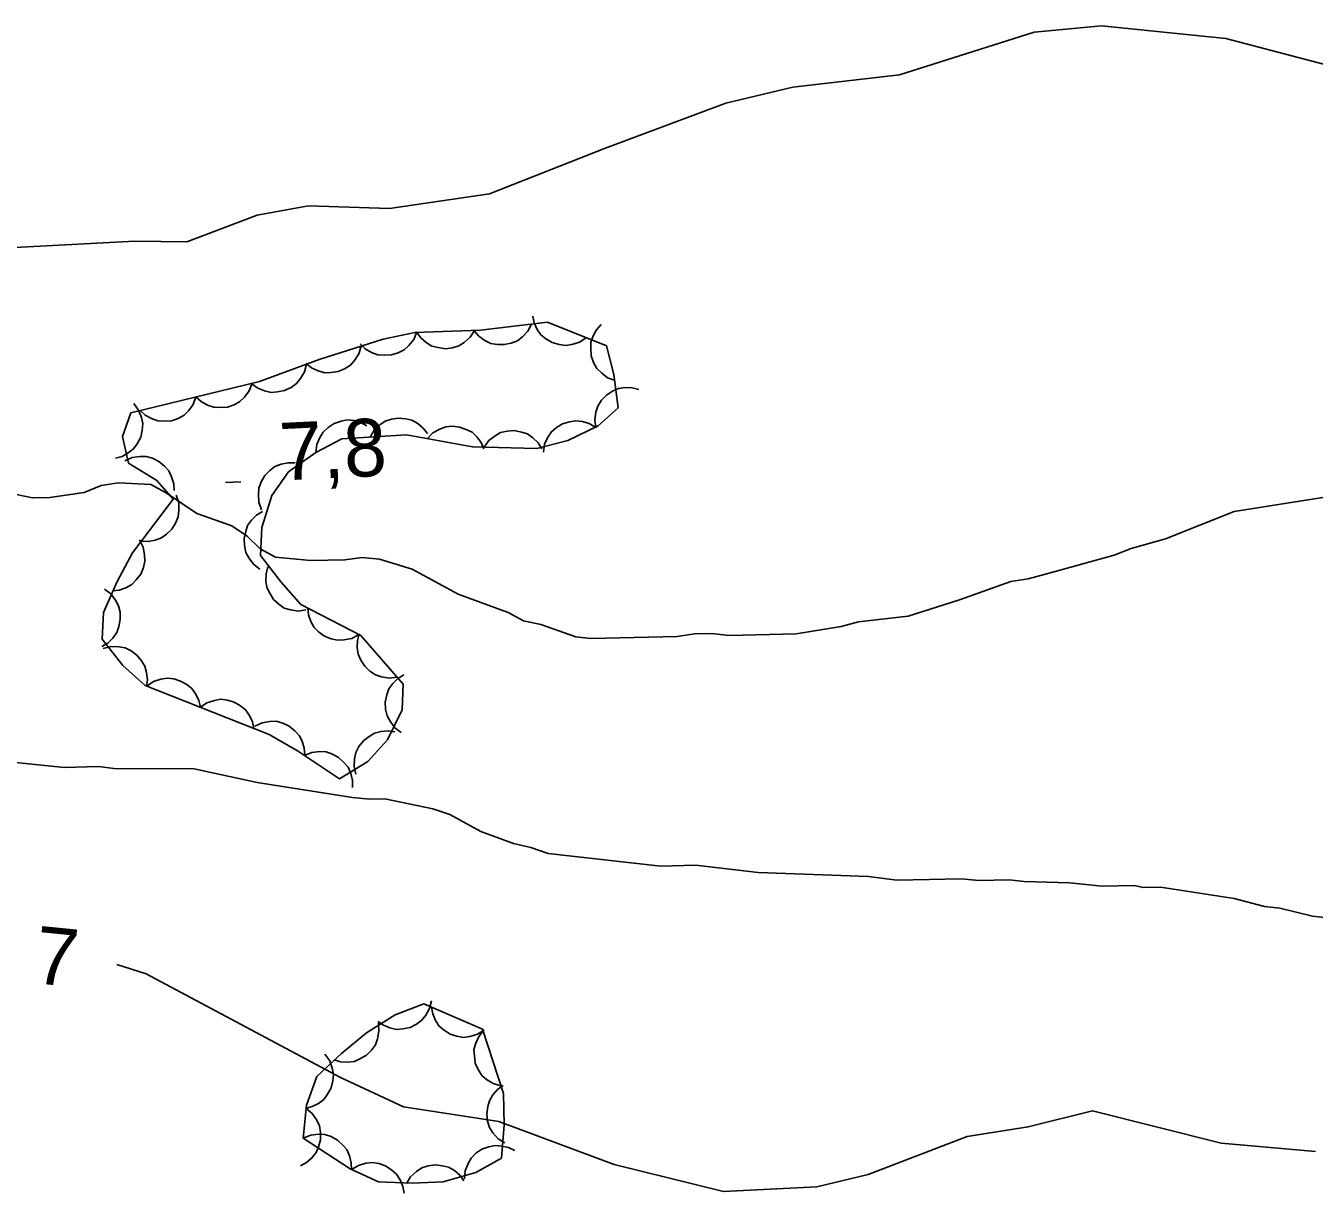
# Model space of a CAD drawing. Extents: x 336540 to 340074, y 5572036 to 5573747.
# Drawn here: x 337020.3 to 337087.4, y 5573140.7 to 5573201.5 of the extents above; entities that cross this region are included whole.
import ezdxf

# ---------------------------------------------------------------- set-up
doc = ezdxf.new("R2010")
doc.units = 0
for name, color, linetype in [('Niveau 2', 7, 'Continuous'), ('Niveau 3', 7, 'Continuous'), ('Niveau 44', 7, 'Continuous')]:
    doc.layers.add(name, color=color, linetype=linetype)

msp = doc.modelspace()

# ---------------------------------------------------------------- linework, layer by layer
at = {"layer": 'Niveau 2'}
for points in [[(337072.82, 5573201.18), (337076.34, 5573201.52), (337082.81, 5573200.86), (337090.35, 5573198.87)], [(337072.82, 5573201.18), (337065.81, 5573198.96), (337060.26, 5573198.33), (337056.76, 5573197.49), (337050.44, 5573195.12), (337044.46, 5573192.77), (337039.25, 5573192), (337035.03, 5573192.14), (337032.35, 5573191.66), (337028.69, 5573190.27), (337025.98, 5573190.3), (337019.74, 5573189.97)], [(337083.24, 5573176.22), (337088.29, 5573177.01), (337090.86, 5573177.63), (337093.56, 5573178.03), (337095.13, 5573178.07), (337098.74, 5573177.81), (337102, 5573177.77), (337103.8, 5573177.93), (337104.7, 5573178.17), (337105.59, 5573178.3), (337106.49, 5573178.55), (337109.95, 5573179.98), (337110.72, 5573180.56), (337111.93, 5573181.94), (337114.58, 5573184.14), (337117.14, 5573185.21)], [(337019.74, 5573177.13), (337020.65, 5573176.93), (337021.55, 5573176.95), (337023.34, 5573177.21), (337024.23, 5573177.57), (337025.13, 5573177.71), (337026.82, 5573177.63), (337027.62, 5573177.2), (337029.22, 5573176.11), (337031.03, 5573175.48), (337031.83, 5573174.93), (337032.52, 5573174.27), (337033.32, 5573173.84), (337035.13, 5573173.66), (337036.93, 5573173.7), (337037.82, 5573173.83), (337038.73, 5573173.74), (337040.43, 5573173.21), (337042.82, 5573171.92), (337045.43, 5573170.96), (337046.23, 5573170.53), (337047.13, 5573170.33), (337048.95, 5573169.69), (337049.74, 5573169.6), (337054.24, 5573169.7), (337055.14, 5573169.84), (337056.04, 5573169.86), (337056.94, 5573169.76), (337060.43, 5573169.84), (337062.78, 5573170.23), (337063.68, 5573170.48), (337066.26, 5573170.76), (337068.94, 5573171.61), (337071.62, 5573172.58), (337072.52, 5573172.71), (337073.41, 5573172.95), (337076.99, 5573173.94), (337077.88, 5573174.29), (337079.67, 5573174.79), (337083.24, 5573176.22)], [(337090.59, 5573154.77), (337087.32, 5573155.15), (337085.62, 5573155.56), (337084.83, 5573155.65), (337083.25, 5573156.07), (337079.41, 5573156.65), (337078.51, 5573156.63), (337078.05, 5573156.74), (337076.37, 5573156.7), (337074.67, 5573156.88), (337072.31, 5573156.94), (337071.52, 5573157.04), (337069.94, 5573157), (337069.04, 5573157.09), (337065.67, 5573157.02), (337064.2, 5573157.21), (337058.45, 5573157.42), (337055.18, 5573157.79), (337053.38, 5573157.75), (337047.51, 5573158.4), (337046.61, 5573158.72), (337045.7, 5573158.93), (337044, 5573159.56), (337042.4, 5573160.43), (337041.5, 5573160.74), (337039.01, 5573161.25), (337038.22, 5573161.23), (337037.32, 5573161.32), (337032.35, 5573162.11), (337029.07, 5573162.82), (337024.9, 5573162.84), (337024.11, 5573162.94), (337022.31, 5573162.89), (337019.61, 5573163.17)], [(337025.04, 5573152.62), (337026.58, 5573152.14), (337036.7, 5573146.73), (337039.98, 5573145.21), (337044.94, 5573144.44), (337050.96, 5573142.2), (337056.64, 5573140.8), (337061.51, 5573141.05), (337064.18, 5573141.69), (337069.33, 5573143.66), (337072.52, 5573144.16), (337075.87, 5573145.01), (337082.56, 5573143.32), (337087.48, 5573142.88)]]:
    msp.add_lwpolyline(points, dxfattribs=at)
at = {"layer": 'Niveau 3'}
msp.add_line((337030.71, 5573177.73), (337031.51, 5573177.77), dxfattribs=at)
at = {"layer": 'Niveau 44'}
for points in [[(337035.42, 5573179.29), (337036.76, 5573180), (337040.13, 5573180.21), (337043.58, 5573179.59), (337046.92, 5573179.5), (337048.53, 5573179.92), (337050.11, 5573180.69), (337051.16, 5573181.62), (337050.93, 5573183.36), (337050.56, 5573184.84), (337047.48, 5573186.08), (337043.99, 5573185.66), (337040.57, 5573185.55), (337038.92, 5573185.2), (337035.59, 5573184.14), (337032.48, 5573182.99), (337025.77, 5573181.36), (337025.35, 5573180.12), (337025.65, 5573178.74), (337027.14, 5573177.84), (337027.98, 5573176.87), (337025.86, 5573174.06), (337025.07, 5573172.57), (337024.35, 5573170.96), (337024.29, 5573169.57), (337025.36, 5573168.19), (337026.53, 5573167.16), (337032.99, 5573164.6), (337034.45, 5573163.76), (337036.65, 5573162.3), (337038.12, 5573163.2), (337039.15, 5573164.32), (337039.91, 5573165.89), (337039.97, 5573167.23), (337037.75, 5573169.76), (337034.64, 5573171.38), (337033.61, 5573172.54), (337032.53, 5573173.92), (337032.6, 5573175.38), (337033.12, 5573177.06), (337033.99, 5573178.28), (337035.42, 5573179.29)], [(337046.65, 5573185.98), (337046.46, 5573185.61), (337046.18, 5573185.32), (337045.92, 5573185.11), (337045.59, 5573184.98), (337045.23, 5573184.91), (337044.85, 5573184.92), (337044.52, 5573184.97), (337044.21, 5573185.13), (337043.91, 5573185.35), (337043.67, 5573185.62)], [(337049.49, 5573185.27), (337049.14, 5573185.04), (337048.75, 5573184.92), (337048.43, 5573184.86), (337048.08, 5573184.91), (337047.72, 5573185.02), (337047.4, 5573185.22), (337047.14, 5573185.42), (337046.94, 5573185.7), (337046.78, 5573186.04), (337046.71, 5573186.39)], [(337051.01, 5573183.05), (337050.61, 5573183.19), (337050.29, 5573183.44), (337050.05, 5573183.67), (337049.88, 5573183.98), (337049.76, 5573184.33), (337049.73, 5573184.71), (337049.74, 5573185.04), (337049.86, 5573185.37), (337050.04, 5573185.69), (337050.28, 5573185.96)], [(337040.67, 5573185.57), (337040.51, 5573185.18), (337040.26, 5573184.87), (337040.02, 5573184.64), (337039.7, 5573184.48), (337039.35, 5573184.38), (337038.97, 5573184.36), (337038.64, 5573184.38), (337038.31, 5573184.51), (337037.99, 5573184.7), (337037.73, 5573184.95)], [(337043.67, 5573185.65), (337043.45, 5573185.3), (337043.14, 5573185.03), (337042.86, 5573184.85), (337042.53, 5573184.75), (337042.16, 5573184.7), (337041.78, 5573184.76), (337041.46, 5573184.83), (337041.16, 5573185.02), (337040.88, 5573185.26), (337040.67, 5573185.55)], [(337037.77, 5573184.83), (337037.65, 5573184.43), (337037.42, 5573184.09), (337037.21, 5573183.84), (337036.91, 5573183.65), (337036.57, 5573183.51), (337036.19, 5573183.46), (337035.86, 5573183.45), (337035.53, 5573183.54), (337035.19, 5573183.7), (337034.91, 5573183.92)], [(337034.92, 5573183.89), (337034.82, 5573183.49), (337034.61, 5573183.14), (337034.41, 5573182.88), (337034.12, 5573182.67), (337033.78, 5573182.52), (337033.41, 5573182.45), (337033.08, 5573182.42), (337032.74, 5573182.5), (337032.4, 5573182.64), (337032.1, 5573182.85)], [(337032.09, 5573182.9), (337031.94, 5573182.5), (337031.7, 5573182.18), (337031.46, 5573181.95), (337031.16, 5573181.78), (337030.81, 5573181.66), (337030.42, 5573181.63), (337030.1, 5573181.65), (337029.77, 5573181.76), (337029.44, 5573181.95), (337029.17, 5573182.19)], [(337049.99, 5573180.58), (337049.94, 5573181), (337050, 5573181.4), (337050.1, 5573181.71), (337050.29, 5573182.01), (337050.55, 5573182.28), (337050.87, 5573182.48), (337051.17, 5573182.62), (337051.52, 5573182.67), (337051.89, 5573182.66), (337052.24, 5573182.57)], [(337025.93, 5573181.84), (337026.18, 5573181.5), (337026.33, 5573181.12), (337026.4, 5573180.8), (337026.37, 5573180.45), (337026.29, 5573180.09), (337026.1, 5573179.75), (337025.92, 5573179.48), (337025.64, 5573179.27), (337025.32, 5573179.09), (337024.97, 5573179)], [(337029.17, 5573182.19), (337029.03, 5573181.8), (337028.78, 5573181.47), (337028.55, 5573181.24), (337028.24, 5573181.07), (337027.89, 5573180.95), (337027.51, 5573180.93), (337027.18, 5573180.94), (337026.85, 5573181.06), (337026.53, 5573181.24), (337026.26, 5573181.48)], [(337035.42, 5573179.29), (337035.46, 5573179.71), (337035.62, 5573180.08), (337035.79, 5573180.36), (337036.05, 5573180.6), (337036.36, 5573180.8), (337036.73, 5573180.92), (337037.04, 5573180.99), (337037.39, 5573180.96), (337037.75, 5573180.86), (337038.07, 5573180.69)], [(337038.24, 5573180.09), (337038.45, 5573180.45), (337038.75, 5573180.73), (337039.02, 5573180.92), (337039.36, 5573181.03), (337039.72, 5573181.08), (337040.1, 5573181.04), (337040.42, 5573180.97), (337040.73, 5573180.8), (337041.01, 5573180.56), (337041.23, 5573180.28)], [(337041.22, 5573180.01), (337041.51, 5573180.31), (337041.87, 5573180.51), (337042.18, 5573180.63), (337042.53, 5573180.66), (337042.89, 5573180.62), (337043.25, 5573180.49), (337043.55, 5573180.35), (337043.8, 5573180.11), (337044.03, 5573179.81), (337044.17, 5573179.48)], [(337047.27, 5573179.31), (337047.33, 5573179.72), (337047.5, 5573180.09), (337047.68, 5573180.37), (337047.94, 5573180.6), (337048.26, 5573180.79), (337048.63, 5573180.89), (337048.95, 5573180.95), (337049.3, 5573180.91), (337049.65, 5573180.8), (337049.97, 5573180.62)], [(337044.18, 5573179.57), (337044.42, 5573179.91), (337044.75, 5573180.16), (337045.03, 5573180.33), (337045.38, 5573180.41), (337045.75, 5573180.43), (337046.12, 5573180.35), (337046.43, 5573180.26), (337046.72, 5573180.06), (337046.99, 5573179.8), (337047.18, 5573179.49)], [(337025.46, 5573178.86), (337025.84, 5573179.03), (337026.24, 5573179.09), (337026.57, 5573179.09), (337026.91, 5573178.99), (337027.24, 5573178.83), (337027.53, 5573178.58), (337027.75, 5573178.34), (337027.9, 5573178.02), (337028.01, 5573177.66), (337028.03, 5573177.31)], [(337032.59, 5573176.31), (337032.44, 5573176.71), (337032.42, 5573177.11), (337032.44, 5573177.44), (337032.56, 5573177.77), (337032.75, 5573178.09), (337033.02, 5573178.36), (337033.28, 5573178.56), (337033.61, 5573178.69), (337033.97, 5573178.76), (337034.33, 5573178.76)], [(337028.13, 5573177.07), (337028.27, 5573176.67), (337028.28, 5573176.27), (337028.25, 5573175.94), (337028.11, 5573175.61), (337027.92, 5573175.3), (337027.64, 5573175.04), (337027.38, 5573174.84), (337027.05, 5573174.72), (337026.68, 5573174.66), (337026.32, 5573174.67)], [(337032.5, 5573173.22), (337032.16, 5573173.47), (337031.92, 5573173.8), (337031.76, 5573174.09), (337031.69, 5573174.44), (337031.68, 5573174.81), (337031.76, 5573175.18), (337031.86, 5573175.49), (337032.07, 5573175.77), (337032.33, 5573176.03), (337032.64, 5573176.22)], [(337026.22, 5573174.74), (337026.42, 5573174.37), (337026.49, 5573173.97), (337026.51, 5573173.64), (337026.43, 5573173.3), (337026.29, 5573172.96), (337026.06, 5573172.66), (337025.83, 5573172.42), (337025.52, 5573172.25), (337025.17, 5573172.13), (337024.82, 5573172.09)], [(337034.9, 5573171.09), (337034.49, 5573171.03), (337034.09, 5573171.1), (337033.77, 5573171.19), (337033.48, 5573171.39), (337033.21, 5573171.64), (337033.01, 5573171.97), (337032.86, 5573172.26), (337032.81, 5573172.61), (337032.82, 5573172.98), (337032.91, 5573173.33)], [(337024.4, 5573172.18), (337024.74, 5573171.93), (337024.98, 5573171.6), (337025.14, 5573171.31), (337025.22, 5573170.97), (337025.23, 5573170.6), (337025.15, 5573170.23), (337025.05, 5573169.92), (337024.84, 5573169.63), (337024.58, 5573169.37), (337024.27, 5573169.18)], [(337037.65, 5573169.81), (337037.28, 5573169.61), (337036.88, 5573169.53), (337036.55, 5573169.51), (337036.21, 5573169.59), (337035.87, 5573169.73), (337035.56, 5573169.96), (337035.33, 5573170.18), (337035.15, 5573170.49), (337035.03, 5573170.84), (337034.99, 5573171.2)], [(337039.65, 5573167.59), (337039.24, 5573167.54), (337038.84, 5573167.61), (337038.52, 5573167.71), (337038.23, 5573167.9), (337037.96, 5573168.16), (337037.76, 5573168.48), (337037.62, 5573168.78), (337037.57, 5573169.13), (337037.58, 5573169.5), (337037.67, 5573169.85)], [(337024.34, 5573169.09), (337024.75, 5573169.19), (337025.15, 5573169.17), (337025.48, 5573169.12), (337025.79, 5573168.96), (337026.09, 5573168.74), (337026.33, 5573168.44), (337026.51, 5573168.17), (337026.6, 5573167.83), (337026.64, 5573167.46), (337026.59, 5573167.1)], [(337039.86, 5573164.71), (337039.52, 5573164.96), (337039.28, 5573165.29), (337039.12, 5573165.58), (337039.05, 5573165.92), (337039.03, 5573166.29), (337039.11, 5573166.67), (337039.21, 5573166.98), (337039.42, 5573167.26), (337039.68, 5573167.52), (337039.99, 5573167.71)], [(337026.61, 5573167.13), (337026.95, 5573167.36), (337027.34, 5573167.49), (337027.67, 5573167.54), (337028.02, 5573167.5), (337028.37, 5573167.39), (337028.7, 5573167.2), (337028.96, 5573167), (337029.16, 5573166.71), (337029.32, 5573166.38), (337029.4, 5573166.02)], [(337029.4, 5573166.02), (337029.74, 5573166.26), (337030.13, 5573166.38), (337030.46, 5573166.44), (337030.81, 5573166.4), (337031.16, 5573166.29), (337031.49, 5573166.09), (337031.75, 5573165.89), (337031.95, 5573165.6), (337032.11, 5573165.27), (337032.19, 5573164.92)], [(337032.24, 5573165.03), (337032.62, 5573165.21), (337033.02, 5573165.28), (337033.35, 5573165.29), (337033.69, 5573165.2), (337034.02, 5573165.04), (337034.32, 5573164.8), (337034.55, 5573164.56), (337034.7, 5573164.25), (337034.81, 5573163.89), (337034.84, 5573163.53)], [(337037.5, 5573162.53), (337037.41, 5573162.93), (337037.43, 5573163.34), (337037.5, 5573163.66), (337037.66, 5573163.98), (337037.89, 5573164.27), (337038.19, 5573164.5), (337038.47, 5573164.67), (337038.81, 5573164.76), (337039.18, 5573164.79), (337039.53, 5573164.74)], [(337034.83, 5573163.51), (337035.21, 5573163.67), (337035.62, 5573163.71), (337035.95, 5573163.7), (337036.28, 5573163.58), (337036.6, 5573163.41), (337036.88, 5573163.14), (337037.1, 5573162.9), (337037.23, 5573162.57), (337037.32, 5573162.21), (337037.33, 5573161.85)], [(337034.76, 5573143.58), (337037.2, 5573141.98), (337038.68, 5573141.31), (337040.43, 5573141.23), (337042.05, 5573141.31), (337043.74, 5573141.79), (337045.08, 5573142.54), (337045.23, 5573144.28), (337045.18, 5573145.91), (337044.09, 5573149.25), (337041.03, 5573150.58), (337039.54, 5573150.01), (337038.06, 5573149.07), (337036.75, 5573147.99), (337035.47, 5573146.79), (337034.93, 5573145.3), (337034.76, 5573143.58)], [(337041.44, 5573150.74), (337041.34, 5573150.33), (337041.14, 5573149.98), (337040.94, 5573149.72), (337040.65, 5573149.51), (337040.32, 5573149.35), (337039.94, 5573149.27), (337039.62, 5573149.24), (337039.27, 5573149.32), (337038.93, 5573149.46), (337038.64, 5573149.66)], [(337044.18, 5573149.21), (337043.83, 5573148.99), (337043.44, 5573148.88), (337043.11, 5573148.83), (337042.76, 5573148.89), (337042.41, 5573149), (337042.09, 5573149.21), (337041.84, 5573149.42), (337041.65, 5573149.71), (337041.5, 5573150.05), (337041.43, 5573150.41)], [(337038.67, 5573149.57), (337038.7, 5573149.15), (337038.62, 5573148.75), (337038.52, 5573148.44), (337038.31, 5573148.16), (337038.05, 5573147.9), (337037.71, 5573147.71), (337037.42, 5573147.58), (337037.07, 5573147.54), (337036.7, 5573147.56), (337036.35, 5573147.66)], [(337045.05, 5573146.3), (337044.65, 5573146.42), (337044.31, 5573146.64), (337044.06, 5573146.85), (337043.87, 5573147.15), (337043.72, 5573147.49), (337043.67, 5573147.87), (337043.65, 5573148.19), (337043.74, 5573148.53), (337043.9, 5573148.87), (337044.12, 5573149.16)], [(337035.89, 5573147.95), (337036.14, 5573147.61), (337036.27, 5573147.23), (337036.34, 5573146.91), (337036.3, 5573146.56), (337036.21, 5573146.2), (337036.02, 5573145.87), (337035.83, 5573145.6), (337035.55, 5573145.39), (337035.22, 5573145.22), (337034.87, 5573145.13)], [(337045.26, 5573143.33), (337044.91, 5573143.55), (337044.64, 5573143.86), (337044.46, 5573144.13), (337044.36, 5573144.47), (337044.32, 5573144.84), (337044.37, 5573145.22), (337044.45, 5573145.53), (337044.63, 5573145.83), (337044.88, 5573146.11), (337045.17, 5573146.32)], [(337034.91, 5573145.12), (337035.23, 5573144.86), (337035.46, 5573144.52), (337035.6, 5573144.22), (337035.66, 5573143.87), (337035.65, 5573143.5), (337035.55, 5573143.13), (337035.43, 5573142.83), (337035.21, 5573142.55), (337034.93, 5573142.31), (337034.62, 5573142.14)], [(337034.76, 5573143.58), (337035.15, 5573143.74), (337035.55, 5573143.78), (337035.88, 5573143.77), (337036.21, 5573143.66), (337036.54, 5573143.48), (337036.82, 5573143.22), (337037.03, 5573142.98), (337037.17, 5573142.65), (337037.26, 5573142.29), (337037.27, 5573141.93)], [(337043.15, 5573141.46), (337043.19, 5573141.88), (337043.34, 5573142.26), (337043.5, 5573142.54), (337043.75, 5573142.79), (337044.06, 5573143), (337044.42, 5573143.12), (337044.74, 5573143.2), (337045.09, 5573143.17), (337045.45, 5573143.09), (337045.77, 5573142.93)], [(337037.27, 5573141.95), (337037.63, 5573142.16), (337038.02, 5573142.27), (337038.35, 5573142.31), (337038.7, 5573142.25), (337039.05, 5573142.13), (337039.37, 5573141.91), (337039.62, 5573141.7), (337039.8, 5573141.41), (337039.95, 5573141.06), (337040.01, 5573140.71)], [(337040.14, 5573141.22), (337040.35, 5573141.57), (337040.66, 5573141.84), (337040.93, 5573142.03), (337041.26, 5573142.14), (337041.63, 5573142.19), (337042.01, 5573142.14), (337042.33, 5573142.07), (337042.63, 5573141.89), (337042.92, 5573141.65), (337043.13, 5573141.36)]]:
    msp.add_lwpolyline(points, dxfattribs=at)

# ---------------------------------------------------------------- texts
at = {"layer": 'Niveau 2'}
msp.add_text('7', height=3, rotation=354.29767, dxfattribs=at).set_placement((337020.66, 5573151.66))
at = {"layer": 'Niveau 3'}
msp.add_text('7,8    ', height=3, rotation=2.7712, dxfattribs=at).set_placement((337033.59, 5573177.83))

doc.saveas('drawing.dxf')
